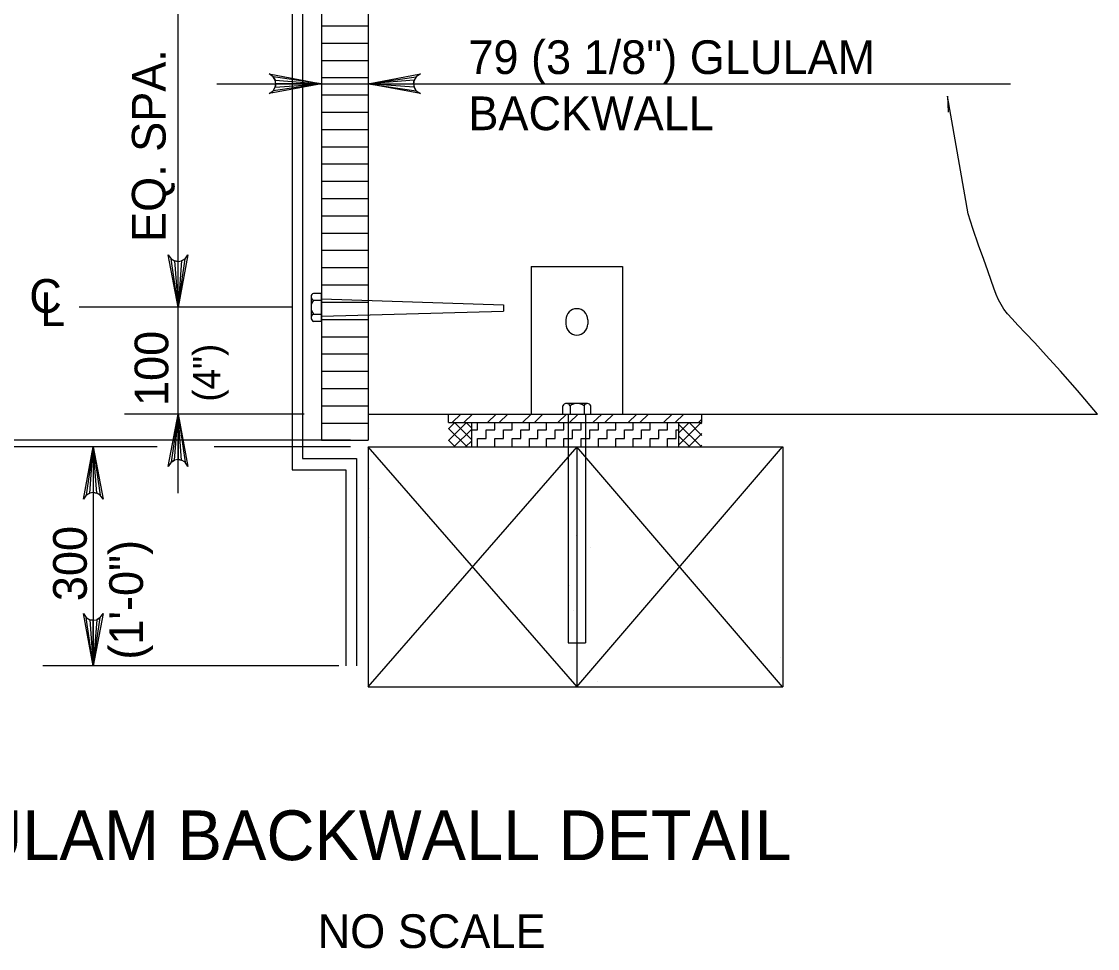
# Model space of a CAD drawing. Extents: x -13 to 81, y -176 to 0.
# Drawn here: x 47.784 to 51.615, y -30.903 to -27.601 of the extents above; entities that cross this region are included whole.
import ezdxf

# ---------------------------------------------------------------- set-up
doc = ezdxf.new("R2010")
doc.units = 0
for name, color, linetype in [('Level 3', 7, 'Continuous'), ('Level 5', 7, 'Continuous'), ('Level 7', 7, 'Continuous'), ('Level 8', 7, 'Continuous')]:
    doc.layers.add(name, color=color, linetype=linetype)

msp = doc.modelspace()

# ---------------------------------------------------------------- linework, layer by layer
at = {"layer": 'Level 3'}
for p, q in [((48.3419, -28.6186), (48.3419, -27.3997)), ((48.4796, -27.8229), (51.306, -27.8229)), ((48.7506, -28.6186), (47.9899, -28.6186)), ((48.3419, -29.2812), (48.3419, -28.6186)), ((48.7912, -28.9992), (48.1512, -28.9992)), ((48.2835, -29.0929), (46.9178, -29.0929)), ((48.7912, -29.0929), (48.4486, -29.0929)), ((48.0123, -29.1164), (47.86, -29.1164)), ((48.04, -29.1164), (48.04, -29.8965)), ((48.9143, -29.8965), (47.86, -29.8965))]:
    msp.add_line(p, q, dxfattribs=at)
for points in [[(48.8528, -27.8229), (48.6663, -27.8578), (48.6807, -27.8479), (48.6881, -27.8354), (48.6902, -27.8229), (48.6881, -27.8104), (48.6807, -27.7979), (48.6663, -27.7879), (48.8528, -27.8229), (48.6807, -27.7979), (48.6881, -27.8104), (48.8528, -27.8229), (48.6902, -27.8229), (48.6881, -27.8354), (48.8528, -27.8229), (48.6807, -27.8479)], [(49.0182, -27.8229), (49.2046, -27.7879), (49.1902, -27.7979), (49.1828, -27.8104), (49.1807, -27.8229), (49.1828, -27.8354), (49.1902, -27.8479), (49.2046, -27.8578), (49.0182, -27.8229), (49.1902, -27.8479), (49.1828, -27.8354), (49.0182, -27.8229), (49.1807, -27.8229), (49.1828, -27.8104), (49.0182, -27.8229), (49.1902, -27.7979)], [(48.3419, -28.6186), (48.307, -28.4322), (48.3169, -28.4465), (48.3294, -28.4539), (48.3419, -28.4561), (48.3544, -28.4539), (48.3669, -28.4465), (48.3768, -28.4322), (48.3419, -28.6186), (48.3669, -28.4465), (48.3544, -28.4539), (48.3419, -28.6186), (48.3419, -28.4561), (48.3294, -28.4539), (48.3419, -28.6186), (48.3169, -28.4465)], [(48.3419, -28.9992), (48.3768, -29.1856), (48.3669, -29.1713), (48.3544, -29.1638), (48.3419, -29.1617), (48.3294, -29.1638), (48.3169, -29.1713), (48.307, -29.1856), (48.3419, -28.9992), (48.3169, -29.1713), (48.3294, -29.1638), (48.3419, -28.9992), (48.3419, -29.1617), (48.3544, -29.1638), (48.3419, -28.9992), (48.3669, -29.1713)], [(48.04, -29.1164), (48.0749, -29.3028), (48.065, -29.2885), (48.0525, -29.2811), (48.04, -29.2789), (48.0275, -29.2811), (48.015, -29.2885), (48.0051, -29.3028), (48.04, -29.1164), (48.015, -29.2885), (48.0275, -29.2811), (48.04, -29.1164), (48.04, -29.2789), (48.0525, -29.2811), (48.04, -29.1164), (48.065, -29.2885)], [(48.04, -29.8965), (48.0051, -29.7101), (48.015, -29.7244), (48.0275, -29.7318), (48.04, -29.734), (48.0525, -29.7318), (48.065, -29.7244), (48.0749, -29.7101), (48.04, -29.8965), (48.065, -29.7244), (48.0525, -29.7318), (48.04, -29.8965), (48.04, -29.734), (48.0275, -29.7318), (48.04, -29.8965), (48.015, -29.7244)]]:
    msp.add_lwpolyline(points, dxfattribs=at)
at = {"layer": 'Level 5'}
for p, q in [((48.8528, -25.1736), (48.8528, -29.0929)), ((48.748, -25.2621), (48.748, -29.198)), ((48.785, -25.3007), (48.785, -29.1582)), ((49.0182, -25.8148), (49.0182, -29.0929)), ((49.5985, -28.4742), (49.9248, -28.4742)), ((49.5985, -28.4742), (49.5985, -28.9992)), ((49.9248, -28.4742), (49.9248, -28.9992)), ((48.8153, -28.5811), (48.8153, -28.657)), ((48.8528, -28.5887), (49.5003, -28.6107)), ((49.5003, -28.6107), (49.5003, -28.6327)), ((48.8528, -28.6502), (49.5003, -28.6327)), ((49.7226, -28.6633), (49.7226, -28.679)), ((49.8008, -28.6633), (49.8008, -28.679)), ((49.0182, -28.9992), (51.6154, -28.9992)), ((49.3053, -28.9992), (50.2072, -28.9992)), ((49.3053, -29.03), (49.3053, -28.9992)), ((49.3182, -29.03), (49.3489, -28.9992)), ((49.3599, -29.03), (49.3907, -28.9992)), ((49.4434, -29.03), (49.4742, -28.9992)), ((49.4852, -29.03), (49.516, -28.9992)), ((49.5687, -29.03), (49.5995, -28.9992)), ((49.6104, -29.03), (49.6412, -28.9992)), ((49.694, -29.03), (49.7248, -28.9992)), ((49.7117, -28.9992), (49.7117, -28.9706)), ((49.7117, -28.9992), (49.8117, -28.9992)), ((49.8, -28.9617), (49.7242, -28.9617)), ((49.7309, -28.9992), (49.7309, -29.8142)), ((49.7357, -29.03), (49.7665, -28.9992)), ((49.7376, -28.9706), (49.7376, -28.9992)), ((49.7875, -28.9706), (49.7875, -28.9992)), ((49.7924, -28.9992), (49.7924, -29.8142)), ((49.8117, -28.9992), (49.8117, -28.9706)), ((49.8192, -29.03), (49.8501, -28.9992)), ((49.861, -29.03), (49.8918, -28.9992)), ((49.9445, -29.03), (49.9753, -28.9992)), ((49.9862, -29.03), (50.0171, -28.9992)), ((50.0698, -29.03), (50.1006, -28.9992)), ((50.1116, -29.03), (50.1423, -28.9992)), ((50.2072, -29.03), (50.2072, -28.9992)), ((49.3053, -29.03), (50.2072, -29.03)), ((49.3053, -29.0934), (49.3687, -29.03)), ((49.3053, -29.0517), (49.327, -29.03)), ((49.3873, -29.0912), (49.326, -29.03)), ((49.3873, -29.0495), (49.3678, -29.03)), ((49.3873, -29.1164), (49.3873, -29.03)), ((49.4082, -29.0552), (49.4082, -29.03)), ((49.4697, -29.0552), (49.4697, -29.03)), ((49.5312, -29.0552), (49.5312, -29.03)), ((49.5927, -29.0552), (49.5927, -29.03)), ((49.6542, -29.0552), (49.6542, -29.03)), ((49.7157, -29.0552), (49.7157, -29.03)), ((49.7772, -29.0552), (49.7772, -29.03)), ((49.8387, -29.0552), (49.8387, -29.03)), ((49.9002, -29.0552), (49.9002, -29.03)), ((49.9617, -29.0552), (49.9617, -29.03)), ((50.0232, -29.0552), (50.0232, -29.03)), ((50.0848, -29.0552), (50.0848, -29.03)), ((50.1254, -29.0667), (50.1622, -29.03)), ((50.1254, -29.1085), (50.2039, -29.03)), ((50.1254, -29.1164), (50.1254, -29.03)), ((50.2058, -29.1164), (50.1254, -29.036)), ((50.2072, -29.0761), (50.1612, -29.03)), ((50.1951, -29.03), (50.2072, -29.0177)), ((50.2072, -29.0343), (50.2029, -29.03)), ((49.3707, -29.1164), (49.3053, -29.0511)), ((49.3241, -29.1164), (49.3873, -29.0532)), ((49.3873, -29.0552), (49.4082, -29.0552)), ((49.4389, -29.0552), (49.4697, -29.0552)), ((49.4389, -29.0859), (49.4389, -29.0552)), ((49.5004, -29.0552), (49.5312, -29.0552)), ((49.5004, -29.0859), (49.5004, -29.0552)), ((49.5619, -29.0552), (49.5927, -29.0552)), ((49.5619, -29.0859), (49.5619, -29.0552)), ((49.6234, -29.0552), (49.6542, -29.0552)), ((49.6234, -29.0859), (49.6234, -29.0552)), ((49.6849, -29.0552), (49.7157, -29.0552)), ((49.6849, -29.0859), (49.6849, -29.0552)), ((49.7465, -29.0552), (49.7772, -29.0552)), ((49.7465, -29.0859), (49.7465, -29.0552)), ((49.808, -29.0552), (49.8387, -29.0552)), ((49.808, -29.0859), (49.808, -29.0552)), ((49.8695, -29.0552), (49.9002, -29.0552)), ((49.8695, -29.0859), (49.8695, -29.0552)), ((49.931, -29.0552), (49.9617, -29.0552)), ((49.931, -29.0859), (49.931, -29.0552)), ((49.9925, -29.0552), (50.0232, -29.0552)), ((49.9925, -29.0859), (49.9925, -29.0552)), ((50.054, -29.0552), (50.0848, -29.0552)), ((50.054, -29.0859), (50.054, -29.0552)), ((50.1156, -29.0552), (50.1253, -29.0552)), ((50.1156, -29.0859), (50.1156, -29.0552)), ((50.1593, -29.1164), (50.2072, -29.0684)), ((49.3289, -29.1164), (49.3053, -29.0928)), ((49.3658, -29.1164), (49.3873, -29.0951)), ((49.4082, -29.0859), (49.4389, -29.0859)), ((49.4082, -29.1164), (49.4082, -29.0859)), ((49.4697, -29.0859), (49.5004, -29.0859)), ((49.4697, -29.1164), (49.4697, -29.0859)), ((49.5312, -29.0859), (49.5619, -29.0859)), ((49.5312, -29.1164), (49.5312, -29.0859)), ((49.5927, -29.0859), (49.6234, -29.0859)), ((49.5927, -29.1164), (49.5927, -29.0859)), ((49.6542, -29.0859), (49.6849, -29.0859)), ((49.6542, -29.1164), (49.6542, -29.0859)), ((49.7157, -29.0859), (49.7465, -29.0859)), ((49.7157, -29.1164), (49.7157, -29.0859)), ((49.7772, -29.0859), (49.808, -29.0859)), ((49.7772, -29.1164), (49.7772, -29.0859)), ((49.8387, -29.0859), (49.8695, -29.0859)), ((49.8387, -29.1164), (49.8387, -29.0859)), ((49.9002, -29.0859), (49.931, -29.0859)), ((49.9002, -29.1164), (49.9002, -29.0859)), ((49.9617, -29.0859), (49.9925, -29.0859)), ((49.9617, -29.1164), (49.9617, -29.0859)), ((50.0232, -29.0859), (50.054, -29.0859)), ((50.0232, -29.1164), (50.0232, -29.0859)), ((50.0848, -29.0859), (50.1156, -29.0859)), ((50.0848, -29.1164), (50.0848, -29.0859)), ((50.1641, -29.1164), (50.1254, -29.0777)), ((50.201, -29.1164), (50.2072, -29.1102)), ((49.0181, -29.1164), (49.7616, -29.9703)), ((49.7616, -29.1164), (49.0181, -29.9703)), ((49.0182, -29.1164), (50.4946, -29.1164)), ((49.0182, -29.1164), (49.0182, -29.9703)), ((49.7616, -29.1164), (49.7616, -29.9703)), ((49.7616, -29.9703), (50.4945, -29.1164)), ((50.4945, -29.9703), (49.7616, -29.1164)), ((50.1388, -29.1166), (50.1388, -29.1166)), ((50.4946, -29.1164), (50.4946, -29.9703)), ((48.785, -29.1582), (48.9768, -29.1582)), ((48.9768, -29.1582), (48.9768, -29.8965)), ((48.748, -29.198), (48.9398, -29.198)), ((48.9398, -29.198), (48.9398, -29.8965)), ((49.0233, -29.2634), (49.0233, -29.2634)), ((49.0222, -29.4398), (49.0222, -29.4398)), ((49.7597, -29.4321), (49.7597, -29.4321)), ((49.8103, -29.4731), (49.8103, -29.4731)), ((49.7351, -29.6111), (49.7351, -29.6111)), ((49.7503, -29.6989), (49.7503, -29.6989)), ((49.7309, -29.8142), (49.7924, -29.8142)), ((50.4867, -29.8675), (50.4867, -29.8675)), ((49.8357, -29.9533), (49.8357, -29.9533)), ((49.0182, -29.9703), (50.4946, -29.9703))]:
    msp.add_line(p, q, dxfattribs=at)
msp.add_lwpolyline([(49.8197, -25.8148), (49.8032, -25.8148), (49.0182, -25.8148), (49.0182, -28.3787)], dxfattribs=at)
for centre, radius, start, end in [((48.8279, -28.5816), 0.0126, 107.4518, 252.5482), ((48.855, -28.6186), 0.0397, 141.05, 218.95), ((48.8292, -28.6565), 0.0139, 111.2869, 178.1729), ((49.7616, -28.6633), 0.039, 0, 180), ((48.8292, -28.6565), 0.0139, 178.1729, 248.7131), ((49.7616, -28.679), 0.039, 180, 0), ((49.7246, -28.9756), 0.0139, 88.1729, 158.7131), ((49.7246, -28.9756), 0.0139, 21.2869, 88.1729), ((49.7625, -29.0015), 0.0398, 51.05, 128.95), ((49.7995, -28.9744), 0.0126, 17.4518, 162.5482)]:
    msp.add_arc(centre, radius, start, end, dxfattribs=at)
at = {"layer": 'Level 7'}
for p, q in [((48.8528, -27.6165), (49.0182, -27.6165)), ((48.8528, -27.6781), (49.0182, -27.6781)), ((48.8528, -27.7396), (49.0182, -27.7396)), ((48.8528, -27.8011), (49.0182, -27.8011)), ((48.8528, -27.8626), (49.0182, -27.8626)), ((48.8528, -27.9241), (49.0182, -27.9241)), ((48.8528, -27.9857), (49.0182, -27.9857)), ((48.8528, -28.0472), (49.0182, -28.0472)), ((48.8528, -28.1087), (49.0182, -28.1087)), ((48.8528, -28.1702), (49.0182, -28.1702)), ((48.8528, -28.2317), (49.0182, -28.2317)), ((48.8528, -28.2933), (49.0182, -28.2933)), ((48.8528, -28.3547), (49.0182, -28.3547)), ((48.8528, -28.4162), (49.0182, -28.4162)), ((48.8528, -28.4778), (49.0182, -28.4778)), ((48.8528, -28.5392), (49.0182, -28.5392)), ((48.8528, -28.5695), (48.8242, -28.5695)), ((48.8528, -28.6695), (48.8528, -28.5695)), ((48.8242, -28.5936), (48.8528, -28.5936)), ((48.8528, -28.6007), (49.0182, -28.6007)), ((48.8242, -28.6436), (48.8528, -28.6436)), ((48.8528, -28.6695), (48.8242, -28.6695)), ((48.8528, -28.6623), (49.0182, -28.6623)), ((48.8528, -28.7238), (49.0182, -28.7238)), ((48.8528, -28.7853), (49.0182, -28.7853)), ((48.8528, -28.8468), (49.0182, -28.8468)), ((48.8528, -28.9083), (49.0182, -28.9083)), ((48.8528, -28.9699), (49.0182, -28.9699)), ((48.8528, -29.0314), (49.0182, -29.0314)), ((48.8528, -29.0929), (49.0182, -29.0929))]:
    msp.add_line(p, q, dxfattribs=at)
for points in [[(51.1554, -28.2866), (51.0813, -27.8669), (51.0836, -27.924)], [(51.6154, -28.9992), (51.5437, -28.9155), (51.4832, -28.8466), (51.4331, -28.7907), (51.3919, -28.7461), (51.3588, -28.7107), (51.3323, -28.6828), (51.3116, -28.6605), (51.2953, -28.642), (51.2825, -28.6254), (51.2721, -28.6094), (51.2632, -28.5926), (51.2549, -28.5736), (51.2464, -28.551), (51.2368, -28.5236), (51.2251, -28.4898), (51.2103, -28.4485), (51.1921, -28.3983), (51.1714, -28.3383), (51.1554, -28.2866)]]:
    msp.add_lwpolyline(points, dxfattribs=at)
at = {"layer": 'Level 8'}
for p, q in [((48.9557, -29.0929), (46.9151, -29.0929)), ((48.2675, -29.1164), (46.915, -29.1164)), ((48.9556, -29.1164), (48.4699, -29.1164))]:
    msp.add_line(p, q, dxfattribs=at)

# ---------------------------------------------------------------- texts
at = {"layer": 'Level 3'}
for s, height, p in [('79 (3 1/8") GLULAM', 0.12, (49.3755, -27.7883)), ('BACKWALL', 0.12, (49.3755, -27.9883)), ('C', 0.12, (47.8121, -28.6387)), ('L', 0.12, (47.851, -28.6857)), ('GLULAM BACKWALL DETAIL', 0.177167, (47.3004, -30.5882)), ('NO SCALE', 0.12, (48.8388, -30.9011))]:
    msp.add_text(s, height=height, dxfattribs=at).set_placement(p)
for s, height, p in [('EQ. SPA.', 0.12, (48.2975, -28.3864)), ('100', 0.12, (48.3072, -28.9707)), ('(4")', 0.09774, (48.4928, -28.9552)), ('300', 0.12, (48.0169, -29.6657)), ('(1\'-0")', 0.12, (48.2169, -29.8741))]:
    msp.add_text(s, height=height, rotation=90, dxfattribs=at).set_placement(p)

doc.saveas('drawing.dxf')
